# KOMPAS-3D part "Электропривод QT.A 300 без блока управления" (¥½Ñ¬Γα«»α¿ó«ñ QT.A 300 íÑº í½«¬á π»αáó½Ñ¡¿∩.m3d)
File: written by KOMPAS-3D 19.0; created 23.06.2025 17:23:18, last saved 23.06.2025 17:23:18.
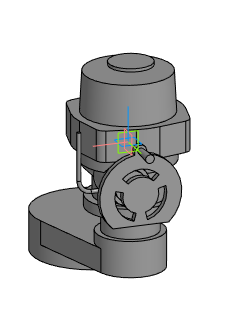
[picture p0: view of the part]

Document properties: Автор: Евгений; Полное имя файла: E:\Dendor Работа Сачек\3D для проектировщиков\3.5 Тип QT.А Электропривод\stp_Электропривод QT.A без блока управления\Электропривод QT.A 300 без блока управления.m3d

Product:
- Part/product: Электропривод QT.A 300 без блока управления

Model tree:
1. Операция без истории:1  (labels: Электропривод QT.A 300 без блока управления)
